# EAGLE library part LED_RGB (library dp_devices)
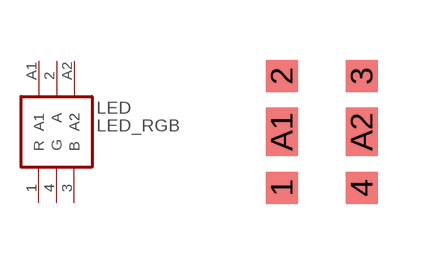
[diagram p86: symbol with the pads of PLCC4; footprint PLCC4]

Designator prefix LED

## LED_RGB  [PLCC4]
1  R
2  A
3  B
4  G
A1  A1
A2  A2

## Footprint PLCC4 (pad centres in mm)
smd 0.8 x 0.8: 1 -1,-1.4; 2 -1,1.4; 3 1,1.4; 4 1,-1.4
smd 0.8 x 1.2: A1 -1,0; A2 1,0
